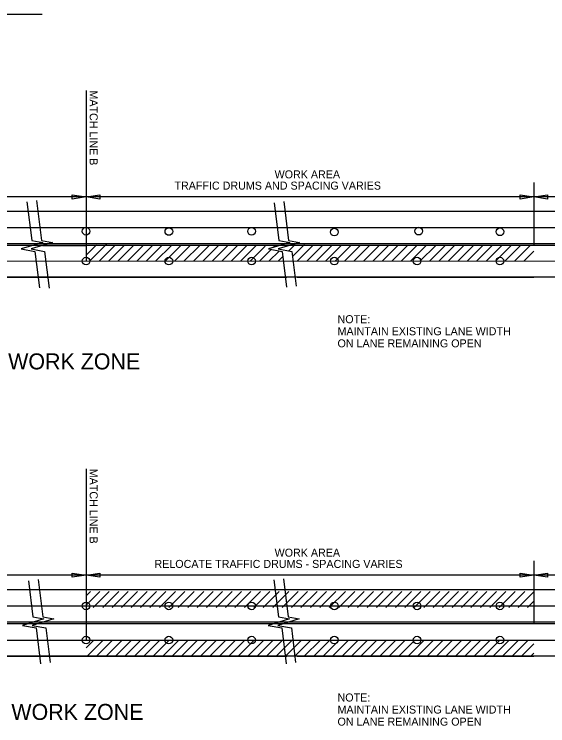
# Model space of a CAD drawing. Extents: x 1930579 to 1938013, y 596452 to 597673.
# Drawn here: x 1934133 to 1934532, y 596650 to 597183 of the extents above; entities that cross this region are included whole.
import ezdxf

# ---------------------------------------------------------------- set-up
doc = ezdxf.new("R2010")
doc.units = 0
doc.layers.add('Default', color=7, linetype='Continuous')
doc.layers.add('R_Border', color=7, linetype='Continuous')

msp = doc.modelspace()

# ---------------------------------------------------------------- linework, layer by layer
at = {"layer": 'Default'}
for p, q in [((1934025.15, 597183.38), (1934153.46, 597183.38)), ((1934186.36, 597126.26), (1934186.36, 597007.89)), ((1934186.36, 597058.93), (1934186.36, 597007.89)), ((1934186.36, 597058.92), (1934186.36, 597007.89)), ((1934186.36, 597058.92), (1934186.36, 596998.31)), ((1934521.71, 597057.24), (1934521.71, 597010.74)), ((1934176.06, 597044.9), (1934176.06, 597048)), ((1934176.06, 597048), (1934186.36, 597046.45)), ((1934186.36, 597046.45), (1934196.66, 597048)), ((1934196.66, 597048), (1934196.66, 597044.9)), ((1934511.4, 597044.9), (1934511.4, 597047.99)), ((1934511.4, 597047.99), (1934521.71, 597046.45)), ((1934521.71, 597046.45), (1934532.01, 597048)), ((1934532.01, 597048), (1934532.01, 597044.9)), ((1934186.36, 597046.45), (1933877.75, 597046.45)), ((1934186.36, 597046.45), (1934176.06, 597044.9)), ((1934521.71, 597046.45), (1934186.36, 597046.45)), ((1934196.66, 597044.9), (1934186.36, 597046.45)), ((1934521.71, 597046.45), (1934511.4, 597044.9)), ((1934532.01, 597044.9), (1934521.71, 597046.45)), ((1934686.11, 597046.45), (1934521.71, 597046.45)), ((1934686.11, 597035.46), (1933682.42, 597035.46)), ((1933682.42, 597023.46), (1934686.11, 597023.46)), ((1934686.11, 597011.23), (1933682.42, 597011.23)), ((1934686.11, 597010.08), (1933682.42, 597010.08)), ((1934153.67, 597010.08), (1934186.36, 597010.08)), ((1934186.37, 597009.84), (1934186.84, 597010.31)), ((1934186.54, 597002.93), (1934194.18, 597010.58)), ((1934188.98, 596998.31), (1934201.9, 597011.23)), ((1934196.05, 596998.31), (1934208.05, 597010.31)), ((1934200.98, 597010.31), (1934201.5, 597010.83)), ((1934203.13, 596998.31), (1934215.13, 597010.31)), ((1934210.2, 596998.31), (1934222.2, 597010.31)), ((1934217.27, 596998.31), (1934229.27, 597010.31)), ((1934224.34, 596998.31), (1934236.34, 597010.31)), ((1934231.41, 596998.31), (1934243.41, 597010.31)), ((1934238.48, 596998.31), (1934250.48, 597010.31)), ((1934245.55, 596998.31), (1934257.55, 597010.31)), ((1934252.62, 596998.31), (1934264.62, 597010.31)), ((1934259.69, 596998.31), (1934271.69, 597010.31)), ((1934266.76, 596998.31), (1934278.76, 597010.31)), ((1934273.84, 596998.31), (1934285.84, 597010.31)), ((1934280.91, 596998.31), (1934292.91, 597010.31)), ((1934287.98, 596998.31), (1934299.98, 597010.31)), ((1934295.05, 596998.31), (1934307.05, 597010.31)), ((1934302.12, 596998.31), (1934314.12, 597010.31)), ((1934326.6, 597008.65), (1934328.26, 597010.31)), ((1934338.17, 597006.07), (1934342.86, 597010.77)), ((1934341.14, 597001.97), (1934349.95, 597010.78)), ((1934344.55, 596998.31), (1934356.55, 597010.31)), ((1934351.62, 596998.31), (1934363.62, 597010.31)), ((1934358.69, 596998.31), (1934370.69, 597010.31)), ((1934365.76, 596998.31), (1934377.76, 597010.31)), ((1934372.83, 596998.31), (1934384.83, 597010.31)), ((1934379.9, 596998.31), (1934391.9, 597010.31)), ((1934386.97, 596998.31), (1934398.97, 597010.31)), ((1934394.04, 596998.31), (1934406.04, 597010.31)), ((1934401.12, 596998.31), (1934413.12, 597010.31)), ((1934408.19, 596998.31), (1934420.19, 597010.31)), ((1934415.26, 596998.31), (1934427.26, 597010.31)), ((1934422.33, 596998.31), (1934434.33, 597010.31)), ((1934429.4, 596998.31), (1934441.4, 597010.31)), ((1934436.47, 596998.31), (1934448.47, 597010.31)), ((1934443.54, 596998.31), (1934455.54, 597010.31)), ((1934450.61, 596998.31), (1934462.61, 597010.31)), ((1934457.68, 596998.31), (1934469.68, 597010.31)), ((1934464.75, 596998.31), (1934476.75, 597010.31)), ((1934471.83, 596998.31), (1934483.83, 597010.31)), ((1934478.9, 596998.31), (1934490.9, 597010.31)), ((1934485.97, 596998.31), (1934497.97, 597010.31)), ((1934493.04, 596998.31), (1934505.04, 597010.31)), ((1934500.11, 596998.31), (1934512.11, 597010.31)), ((1934507.18, 596998.31), (1934519.18, 597010.31)), ((1934309.19, 596998.31), (1934320.56, 597009.68)), ((1934316.26, 596998.31), (1934324.95, 597006.99)), ((1934323.33, 596998.31), (1934330.91, 597005.88)), ((1934514.25, 596998.31), (1934521.69, 597005.75)), ((1934330.36, 596998.26), (1934333.6, 597001.5)), ((1933682.42, 596998.31), (1934686.11, 596998.53)), ((1934686.11, 596986.31), (1933682.42, 596986.31)), ((1933947.06, 596986.31), (1934222.13, 596986.31)), ((1934159.38, 596986.31), (1934186.14, 596986.31)), ((1934186.14, 596986.31), (1934336.75, 596986.31)), ((1934344.4, 596986.31), (1934521.71, 596986.31)), ((1934186.36, 596842.77), (1934186.36, 596723.97)), ((1934186.36, 596775.01), (1934186.36, 596723.97)), ((1934186.36, 596775), (1934186.36, 596723.97)), ((1934186.36, 596775), (1934186.36, 596714.39)), ((1934521.71, 596773.75), (1934521.71, 596726.82)), ((1934186.36, 596762.96), (1933877.75, 596762.96)), ((1934176.06, 596761.41), (1934176.06, 596764.51)), ((1934176.06, 596764.51), (1934186.36, 596762.96)), ((1934186.36, 596762.96), (1934176.06, 596761.41)), ((1934186.36, 596762.96), (1934196.66, 596764.51)), ((1934521.71, 596762.96), (1934186.36, 596762.96)), ((1934196.66, 596761.41), (1934186.36, 596762.96)), ((1934196.66, 596764.51), (1934196.66, 596761.41)), ((1934511.4, 596761.41), (1934511.4, 596764.5)), ((1934511.4, 596764.5), (1934521.71, 596762.96)), ((1934521.71, 596762.96), (1934511.4, 596761.41)), ((1934521.71, 596762.96), (1934532.01, 596764.51)), ((1934686.11, 596762.96), (1934521.71, 596762.96)), ((1934532.01, 596761.41), (1934521.71, 596762.96)), ((1934532.01, 596764.51), (1934532.01, 596761.41)), ((1934686.11, 596751.97), (1933682.42, 596751.97)), ((1934186.36, 596740.48), (1934196.7, 596750.82)), ((1934186.36, 596747.55), (1934189.63, 596750.82)), ((1934191.77, 596738.82), (1934203.77, 596750.82)), ((1934198.84, 596738.82), (1934210.84, 596750.82)), ((1934205.91, 596738.82), (1934217.91, 596750.82)), ((1934212.98, 596738.82), (1934224.98, 596750.82)), ((1934220.05, 596738.82), (1934232.05, 596750.82)), ((1934227.13, 596738.82), (1934239.13, 596750.82)), ((1934234.2, 596738.82), (1934246.2, 596750.82)), ((1934241.27, 596738.82), (1934253.27, 596750.82)), ((1934248.34, 596738.82), (1934260.34, 596750.82)), ((1934255.41, 596738.82), (1934267.41, 596750.82)), ((1934262.48, 596738.82), (1934274.48, 596750.82)), ((1934269.55, 596738.82), (1934281.55, 596750.82)), ((1934276.62, 596738.82), (1934288.62, 596750.82)), ((1934283.69, 596738.82), (1934295.69, 596750.82)), ((1934290.76, 596738.82), (1934302.76, 596750.82)), ((1934297.84, 596738.82), (1934309.84, 596750.82)), ((1934304.91, 596738.82), (1934316.91, 596750.82)), ((1934311.98, 596738.82), (1934323.98, 596750.82)), ((1934319.05, 596738.82), (1934331.05, 596750.82)), ((1934326.12, 596738.82), (1934338.12, 596750.82)), ((1934333.19, 596738.82), (1934345.19, 596750.82)), ((1934340.26, 596738.82), (1934352.26, 596750.82)), ((1934347.33, 596738.82), (1934359.33, 596750.82)), ((1934354.4, 596738.82), (1934366.4, 596750.82)), ((1934361.48, 596738.82), (1934373.48, 596750.82)), ((1934368.55, 596738.82), (1934380.55, 596750.82)), ((1934375.62, 596738.82), (1934387.62, 596750.82)), ((1934382.69, 596738.82), (1934394.69, 596750.82)), ((1934389.76, 596738.82), (1934401.76, 596750.82)), ((1934396.83, 596738.82), (1934408.83, 596750.82)), ((1934403.9, 596738.82), (1934415.9, 596750.82)), ((1934410.97, 596738.82), (1934422.97, 596750.82)), ((1934418.04, 596738.82), (1934430.04, 596750.82)), ((1934425.12, 596738.82), (1934437.12, 596750.82)), ((1934432.19, 596738.82), (1934444.19, 596750.82)), ((1934439.26, 596738.82), (1934451.26, 596750.82)), ((1934446.33, 596738.82), (1934458.33, 596750.82)), ((1934453.4, 596738.82), (1934465.4, 596750.82)), ((1934460.47, 596738.82), (1934472.47, 596750.82)), ((1934467.54, 596738.82), (1934479.54, 596750.82)), ((1934474.61, 596738.82), (1934486.61, 596750.82)), ((1934481.68, 596738.82), (1934493.68, 596750.82)), ((1934488.75, 596738.82), (1934500.75, 596750.82)), ((1934495.83, 596738.82), (1934507.83, 596750.82)), ((1934502.9, 596738.82), (1934514.9, 596750.82)), ((1934509.97, 596738.82), (1934521.97, 596750.82)), ((1934517.04, 596738.82), (1934521.71, 596743.49)), ((1933682.42, 596739.97), (1934686.11, 596739.97)), ((1934686.11, 596727.74), (1933682.42, 596727.74)), ((1934686.11, 596726.59), (1933682.42, 596726.59)), ((1933682.42, 596714.39), (1934686.11, 596714.39)), ((1934186.36, 596708.62), (1934192.13, 596714.39)), ((1934187.2, 596702.39), (1934199.2, 596714.39)), ((1934194.27, 596702.39), (1934206.27, 596714.39)), ((1934201.34, 596702.39), (1934213.34, 596714.39)), ((1934208.41, 596702.39), (1934220.41, 596714.39)), ((1934215.48, 596702.39), (1934227.48, 596714.39)), ((1934222.55, 596702.39), (1934234.55, 596714.39)), ((1934229.62, 596702.39), (1934241.62, 596714.39)), ((1934236.69, 596702.39), (1934248.69, 596714.39)), ((1934243.76, 596702.39), (1934255.76, 596714.39)), ((1934250.84, 596702.39), (1934262.84, 596714.39)), ((1934257.91, 596702.39), (1934269.91, 596714.39)), ((1934264.98, 596702.39), (1934276.98, 596714.39)), ((1934272.05, 596702.39), (1934284.05, 596714.39)), ((1934279.12, 596702.39), (1934291.12, 596714.39)), ((1934286.19, 596702.39), (1934298.19, 596714.39)), ((1934293.26, 596702.39), (1934305.26, 596714.39)), ((1934300.33, 596702.39), (1934312.33, 596714.39)), ((1934307.4, 596702.39), (1934319.4, 596714.39)), ((1934314.48, 596702.39), (1934326.48, 596714.39)), ((1934321.55, 596702.39), (1934333.55, 596714.39)), ((1934328.62, 596702.39), (1934340.62, 596714.39)), ((1934335.69, 596702.39), (1934347.69, 596714.39)), ((1934342.76, 596702.39), (1934354.76, 596714.39)), ((1934349.83, 596702.39), (1934361.83, 596714.39)), ((1934356.9, 596702.39), (1934368.9, 596714.39)), ((1934363.97, 596702.39), (1934375.97, 596714.39)), ((1934371.04, 596702.39), (1934383.04, 596714.39)), ((1934378.12, 596702.39), (1934390.12, 596714.39)), ((1934385.19, 596702.39), (1934397.19, 596714.39)), ((1934392.26, 596702.39), (1934404.26, 596714.39)), ((1934399.33, 596702.39), (1934411.33, 596714.39)), ((1934406.4, 596702.39), (1934418.4, 596714.39)), ((1934413.47, 596702.39), (1934425.47, 596714.39)), ((1934420.54, 596702.39), (1934432.54, 596714.39)), ((1934427.61, 596702.39), (1934439.61, 596714.39)), ((1934434.68, 596702.39), (1934446.68, 596714.39)), ((1934441.75, 596702.39), (1934453.75, 596714.39)), ((1934448.83, 596702.39), (1934460.83, 596714.39)), ((1934455.9, 596702.39), (1934467.9, 596714.39)), ((1934462.97, 596702.39), (1934474.97, 596714.39)), ((1934470.04, 596702.39), (1934482.04, 596714.39)), ((1934477.11, 596702.39), (1934489.11, 596714.39)), ((1934484.18, 596702.39), (1934496.18, 596714.39)), ((1934491.25, 596702.39), (1934503.25, 596714.39)), ((1934498.32, 596702.39), (1934510.32, 596714.39)), ((1934505.39, 596702.39), (1934517.39, 596714.39)), ((1934512.47, 596702.39), (1934521.71, 596711.63)), ((1934686.11, 596702.39), (1933682.42, 596702.39)), ((1933947.06, 596702.39), (1934222.13, 596702.39)), ((1934159.38, 596702.39), (1934186.14, 596702.39)), ((1934186.14, 596702.39), (1934336.75, 596702.39)), ((1934344.4, 596702.39), (1934521.71, 596702.39)), ((1934519.54, 596702.39), (1934521.71, 596704.56))]:
    msp.add_line(p, q, dxfattribs=at)
for points in [[(1934142.01, 597042.85), (1934145.63, 597013.83), (1934153.89, 597012.37), (1934137.86, 597007.52), (1934148.06, 597005.57), (1934151.35, 596978.24)], [(1934149.18, 597043.74), (1934152.91, 597013.83), (1934161.17, 597012.37), (1934145.14, 597007.52), (1934155.34, 597005.57), (1934158.64, 596978.14)], [(1934327.26, 597042.15), (1934330.8, 597013.83), (1934339.06, 597012.37), (1934323.03, 597007.52), (1934333.23, 597005.57), (1934336.45, 596978.81)], [(1934334.44, 597043.05), (1934338.09, 597013.83), (1934346.34, 597012.37), (1934330.32, 597007.52), (1934340.52, 597005.57), (1934343.63, 596979.67)], [(1934150.35, 596759.7), (1934153.85, 596731.72), (1934162.1, 596730.26), (1934146.08, 596725.4), (1934156.27, 596723.46), (1934159.39, 596697.56)], [(1934327.02, 596759.49), (1934330.49, 596731.72), (1934338.74, 596730.26), (1934322.72, 596725.4), (1934332.91, 596723.46), (1934336.13, 596696.69)], [(1934334.19, 596760.38), (1934337.77, 596731.72), (1934346.03, 596730.26), (1934330, 596725.4), (1934340.2, 596723.46), (1934343.31, 596697.56)], [(1934143.18, 596758.81), (1934146.56, 596731.72), (1934154.82, 596730.26), (1934138.79, 596725.4), (1934148.99, 596723.46), (1934152.21, 596696.69)]]:
    msp.add_lwpolyline(points, dxfattribs=at)
for centre in [(1934186.36, 597020.8), (1934248.35, 597020.56), (1934310.34, 597020.7), (1934372.33, 597020.12), (1934435.51, 597020.82), (1934496.32, 597020.33), (1934186.36, 596998.42), (1934248.35, 596998.42), (1934310.34, 596998.42), (1934372.33, 596998.42), (1934434.33, 596998.42), (1934496.32, 596998.42), (1934186.36, 596739.96), (1934248.35, 596739.96), (1934310.34, 596739.96), (1934372.33, 596739.96), (1934434.33, 596739.96), (1934496.32, 596739.96), (1934186.36, 596714.39), (1934248.35, 596714.39), (1934310.34, 596714.39), (1934372.33, 596714.39), (1934434.33, 596714.39), (1934496.32, 596714.39)]:
    msp.add_circle(centre, 2.87, dxfattribs=at)

# ---------------------------------------------------------------- texts
for s, height, rotation, p in [('MATCH LINE B', 6, 270, (1934189.06, 597126.26)), ('WORK AREA', 6, 360, (1934327.57, 597060.38)), ('TRAFFIC DRUMS AND SPACING VARIES', 6, 360, (1934252.56, 597051.95)), ('DIVERSION FOR LT. LANE WORK ZONE', 12, 360, (1933922.91, 596917.22)), ('MATCH LINE B', 6, 270, (1934189.06, 596842.77)), ('WORK AREA', 6, 360, (1934327.57, 596776.89)), ('RELOCATE TRAFFIC DRUMS - SPACING VARIES', 6, 360, (1934237.56, 596768.46)), ('DIVERSION FOR RT. LANE WORK ZONE', 12, 360, (1933922.63, 596654.55))]:
    msp.add_text(s, height=height, rotation=rotation, dxfattribs=at).set_placement(p)
at = {"layer": 'R_Border'}
for s, p in [('NOTE:', (1934374.7, 596951.85)), ('MAINTAIN EXISTING LANE WIDTH', (1934374.7, 596942.8)), ('ON LANE REMAINING OPEN', (1934374.7, 596933.75)), ('NOTE:', (1934374.7, 596668.36)), ('MAINTAIN EXISTING LANE WIDTH', (1934374.7, 596659.31)), ('ON LANE REMAINING OPEN', (1934374.7, 596650.26))]:
    msp.add_text(s, height=6, rotation=360, dxfattribs=at).set_placement(p)

doc.saveas('drawing.dxf')
